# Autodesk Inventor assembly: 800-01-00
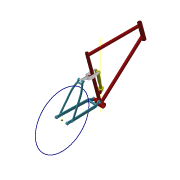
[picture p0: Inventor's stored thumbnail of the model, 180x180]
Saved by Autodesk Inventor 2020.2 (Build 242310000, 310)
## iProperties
Created: 2014-12
Part Number: 800-01-00
Document SubType Name: Assembly
Designer: F.Stasiak
Mass: 1100.88 g
Surface Area: 5668.27 cm^2
Volume: 991.881 cm^3
Density: 1.10989 g/cm^3
Catalog Web Link: www.expertbooks.pl
Manager: www.cadconsulting.pl
Company: Fabian Stasiak CAD Consulting
Author: F.Stasiak
Subject: Zbiór ćwiczeń. Autodesk Inventor 2020. Kurs Professional
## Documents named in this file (7)
- C:\2020_Kurs_Professional\R3 Dynamika\800-01-00.iam
- C:\2020_Kurs_Professional\R3 Dynamika\Komponenty_dyn\800-01-Rama.ipt
- C:\2020_Kurs_Professional\R3 Dynamika\Komponenty_dyn\800-03-Ramię.ipt
- C:\2020_Kurs_Professional\R3 Dynamika\Komponenty_dyn\800-04-Dzwignia.ipt
- C:\2020_Kurs_Professional\R3 Dynamika\Komponenty_dyn\123-010-Amortyzator.ipt
- C:\2020_Kurs_Professional\R3 Dynamika\Komponenty_dyn\123-020-Amortyzator.ipt
- C:\2020_Kurs_Professional\R3 Dynamika\Komponenty_dyn\800-01-01.iam
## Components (6 placed, 6 different names)
1. 800-01-Rama:1 — Zestawiający:14, Zestawiający:15, Zestawiający:16, Zestawiający:19, Zestawiający:20
2. 800-01-01:1 [sub-assembly] — UGIĘCIE
3. 800-03-Ramię:1 — Zestawiający:21
4. 800-04-Dzwignia:1 — Zestawiający:19, Zestawiający:20, Zestawiający:21, Zestawiający:22
5. 123-010-Amortyzator:1 — Zestawiający:9, Zestawiający:13, Zestawiający:14, Zestawiający:15
6. 123-020-Amortyzator:1 — Zestawiający:9, Zestawiający:13, Zestawiający:22
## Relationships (10: Mate 10)
- UGIĘCIE [Mate]: 800-01-01:1
- Zestawiający:9 [Mate]: 123-010-Amortyzator:1 ↔ 123-020-Amortyzator:1
- Zestawiający:13 [Mate]: 123-010-Amortyzator:1 ↔ 123-020-Amortyzator:1
- Zestawiający:14 [Mate]: 800-01-Rama:1 ↔ 123-010-Amortyzator:1
- Zestawiający:15 [Mate]: 800-01-Rama:1 ↔ 123-010-Amortyzator:1
- Zestawiający:16 [Mate]: 800-01-Rama:1
- Zestawiający:19 [Mate]: 800-01-Rama:1 ↔ 800-04-Dzwignia:1
- Zestawiający:20 [Mate]: 800-01-Rama:1 ↔ 800-04-Dzwignia:1
- Zestawiający:21 [Mate]: 800-03-Ramię:1 ↔ 800-04-Dzwignia:1
- Zestawiający:22 [Mate]: 800-04-Dzwignia:1 ↔ 123-020-Amortyzator:1
